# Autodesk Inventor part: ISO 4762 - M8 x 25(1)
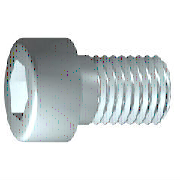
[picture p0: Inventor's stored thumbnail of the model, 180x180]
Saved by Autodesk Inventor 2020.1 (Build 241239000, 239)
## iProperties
Created: 2019-01
Part Number: ISO 4762 - M8 x 25(1)
Material: Edelstahl, 440C
Description: Innensechskantschraube
Document SubType Name: Modeling
Standard: ISO 4762
Designer: lutzd
Standard Revision: Fourth edition 2004-03-01
Standards Organization: ISO
Language: de-DE
Size Designation: M8 x 25
Categories: <MemberInstance><Categories><Category DisplayName="Verbindungselemente" InternalName="e4da775c-781d-43d5-af7c-5136215cf5a6" Mnemonic="FSTN"><Category DisplayNam
Mass: 16.717 g
Surface Area: 12.8469 cm^2
Volume: 2.15703 cm^3
Density: 7.75 g/cm^3
Appearance: Halbpoliert
IsCustomPart: 0
Author: lutzd
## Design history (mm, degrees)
workplane "Work Plane1"
fillet "Fillet2" dims "d30" = 0.1 (= R)
sketch "Skizze1"
  geometry: L1 (-2, 0)-(25, 0); L2 (25, 0)-(25, 4); L3 (25, 4)-(3.125, 4); L4 (3.125, 4)-(2.358, 4); L5 (2.358, 4)-(0, 4); L6 (0, 4)-(0, 6.5); L7 (0, 6.5)-(-8, 6.5); L8 (-8, 6.5)-(-8, 3.464); L9 (-8, 3.464)-(-4, 3.464); L10 (-4, 3.464)-(-2, 0); L11 (-14.6, 0)-(31.6, 0) reference; L12 (0, -1.3)-(0, 7.8) reference; L13 (3.125, 4)-(0, 4)
  constraints: 22 end point, 6 parallel, 2 collinear, 2 perpendicular, 1 horizontal, 1 point on line
  dimensions: "d1" = 21.875 distance from line of L3.end L2 (= GEL); "d2" = 0.76691 distance of L4.end L3.end (computed from GAL); "d3" = 8 distance between parallel lines of L8 L6 (= KOH); "d4" = 4 distance of L8.end L9.end (= INTI); "d5" = 60 deg angle of L10 L1; "d6" = 8 diameter of L3 L1 (= GD); "d7" = 8 diameter of L5 L1 (= BDM); "d8" = 6.9282 diameter of L9 L1 (= 1.1547 x SW); "d9" = 13 diameter of L7 L1 (= KOD); "d26" = 25 distance between parallel lines of L12 L2 (= NLG)
revolve "Körper" sketch "Skizze1" stored, may be unused: angle "d10" = 90 deg
sketch "Skizze2"
  geometry: L1 (0, -9.1)-(0, 9.1) reference; L2 (-9.1, 0)-(9.1, 0) reference; L3 (3.464, 0)-(1.732, -3); L4 (1.732, -3)-(-1.732, -3); L5 (-1.732, -3)-(-3.464, 0); L6 (-3.464, 0)-(-1.732, 3); L7 (-1.732, 3)-(1.732, 3); L8 (1.732, 3)-(3.464, 0); 2 further points
  constraints: 12 end point, 1 coincident, 1 horizontal alignment, 1 point on line, 12 other
extrude "Loch" join sketch "Skizze2" stored distance "d11" = 10; taper "d12" = 0 deg
body "Solid1"
fillet "Rundung1" dims "d17" = 0.8 (= RR)
feature "Gewinde" dims "d13" = 21.875 (= GEL), "d14" = 0
chamfer "Fase1" distance "d15" = 0.76681 (= -0.5 x SPD + 0.5 x GD); stored, may be unused: second distance "d16" = 0.76681 (= GUL), angle "d27" = 45 deg
other parameters: "GD" = 8 [user parameter; used in 2 equation terms], "NLG" = 25 [user parameter; used in 1 equation term], "GEL" = 21.875 [user parameter; used in 2 equation terms], "KOD" = 13 [user parameter; used in 1 equation term], "KOH" = 8 [user parameter; used in 1 equation term], "INTI" = 4 [user parameter; used in 1 equation term], "GAL" = 0.76681 (= 0.61345 x PTC) [user parameter; used in 1 equation term], "GUL" = 0.76681 (= 0.61345 x PTC) [user parameter; used in 1 equation term], "BDM" = 8 (= NND) [user parameter; used in 1 equation term], "SW" = 6 [user parameter; used in 2 equation terms], "RR" = 0.8 [user parameter; used in 1 equation term], "SPD" = 6.46637 (= NND - 1.2269 x PTC) [user parameter; used in 1 equation term], "d19" = 0, "d28" = 0, "d29" = 0, "R" = 0.1 [user parameter; used in 1 equation term], "TOA" = 30 deg [user parameter], "GD1" = 6.46637 (= THREADDIA - 1.2269 x PTC) [user parameter], "THREADDIA" = 8 [user parameter; used in 1 equation term], "FAWI" = 45 deg [user parameter], "TPU" = 8 (computed from PTC) [user parameter], "PTC" = 1.25 [user parameter; used in 5 equation terms], "NND" = 8 [user parameter; used in 2 equation terms], "E0" = 6.93 (= 1.155 x SW) [user parameter]
